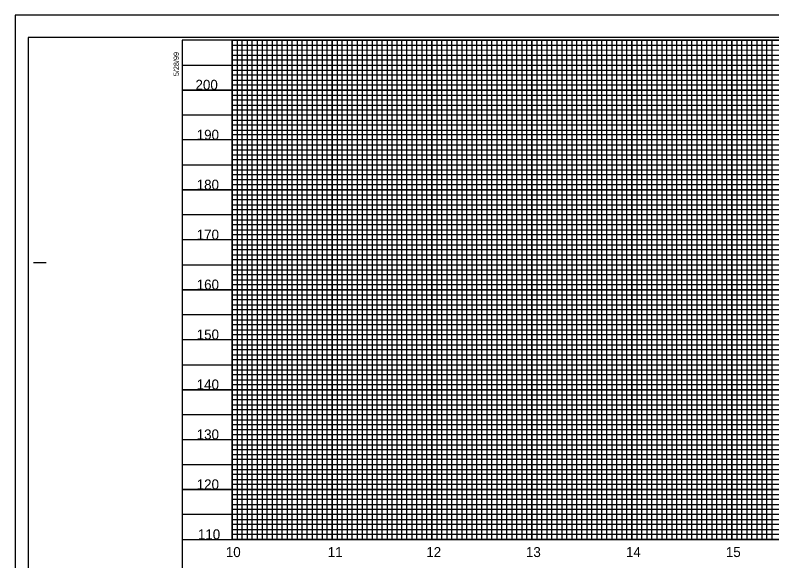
# Model space of a CAD drawing. Extents: x 1779926 to 1781610, y 602514 to 621564.
# Drawn here: x 1779926 to 1780683, y 603068 to 603614 of the extents above; entities that cross this region are included whole.
import ezdxf

# ---------------------------------------------------------------- set-up
doc = ezdxf.new("R2010")
doc.units = 0
for name, color, linetype in [('Exist Vertical Profile Horizontal Axis Label Major', 7, 'Continuous'), ('Exist Vertical Profile Vertical Axis Label', 7, 'Continuous'), ('Scratch_Level_0', 7, 'Continuous'), ('Sheet DOT Grid CELL', 7, 'Continuous'), ('Sheet Layout Profile Border Port 1', 7, 'Continuous'), ('Sheet Plot Border Inside CELL', 7, 'Continuous'), ('Sheet Plot Border Outside CELL', 7, 'Continuous'), ('Sheet Profile CELL', 7, 'Continuous'), ('Sheet Profile Grid Major CELL', 7, 'Continuous'), ('Sheet Profile Grid Middle CELL', 7, 'Continuous'), ('Sheet Profile Grid Minor CELL', 7, 'Continuous')]:
    doc.layers.add(name, color=color, linetype=linetype)

msp = doc.modelspace()

# ---------------------------------------------------------------- linework, layer by layer
at = {"layer": 'Scratch_Level_0'}
msp.add_lwpolyline([(1780142.96, 603089.44), (1780142.96, 603589.44), (1781392.96, 603589.44), (1781392.96, 603364.44), (1781542.96, 603364.44), (1781542.96, 603089.44)], close=True, dxfattribs=at)
at = {"layer": 'Sheet DOT Grid CELL'}
for p, q in [((1780142.96, 603089.45), (1780142.96, 603589.45)), ((1780192.96, 603089.45), (1780192.96, 603589.45)), ((1780242.96, 603089.45), (1780242.96, 603589.45)), ((1780292.96, 603089.45), (1780292.96, 603589.45)), ((1780342.96, 603089.45), (1780342.96, 603589.45)), ((1780392.96, 603089.45), (1780392.96, 603589.45)), ((1780442.96, 603089.45), (1780442.96, 603589.45)), ((1780492.96, 603089.45), (1780492.96, 603589.45)), ((1780542.96, 603089.45), (1780542.96, 603589.45)), ((1780592.96, 603089.45), (1780592.96, 603589.45)), ((1780642.96, 603089.45), (1780642.96, 603589.45)), ((1781392.91, 603539.45), (1780092.96, 603539.45)), ((1781392.91, 603489.45), (1780092.96, 603489.45)), ((1781392.96, 603439.45), (1780092.96, 603439.45)), ((1781392.91, 603389.45), (1780092.96, 603389.45)), ((1781592.96, 603339.45), (1780092.96, 603339.45)), ((1781592.96, 603289.45), (1780092.96, 603289.45)), ((1781592.96, 603239.45), (1780092.96, 603239.45)), ((1781592.96, 603189.45), (1780092.96, 603189.45)), ((1781592.96, 603139.45), (1780092.96, 603139.45))]:
    msp.add_line(p, q, dxfattribs=at)
at = {"layer": 'Sheet Layout Profile Border Port 1'}
msp.add_lwpolyline([(1780142.96, 603589.44), (1781392.91, 603589.45), (1781392.9, 603364.45), (1781542.96, 603364.44), (1781542.96, 603089.45), (1780142.96, 603089.44)], close=True, dxfattribs=at)
msp.add_lwpolyline([(1780142.96, 603428.4), (1780142.96, 603089.45), (1781542.96, 603089.45), (1781542.96, 603364.45)], dxfattribs=at)
at = {"layer": 'Sheet Plot Border Inside CELL'}
msp.add_lwpolyline([(1779938.96, 602536.9), (1781605.46, 602536.9), (1781605.46, 603592), (1779938.96, 603592)], close=True, dxfattribs=at)
at = {"layer": 'Sheet Plot Border Outside CELL'}
msp.add_lwpolyline([(1779925.96, 602514.45), (1781609.96, 602514.45), (1781609.96, 603614.45), (1779925.96, 603614.45)], close=True, dxfattribs=at)
at = {"layer": 'Sheet Profile CELL'}
for p, q in [((1779944.46, 603366.95), (1779956.96, 603366.95)), ((1780092.96, 603089.45), (1781592.96, 603089.45))]:
    msp.add_line(p, q, dxfattribs=at)
msp.add_lwpolyline([(1781592.96, 603589.45), (1780092.96, 603589.45), (1780092.96, 602539.45), (1781592.96, 602539.45)], close=True, dxfattribs=at)
at = {"layer": 'Sheet Profile Grid Major CELL'}
for points in [[(1780142.96, 603589.45), (1780142.96, 603089.45), (1780192.96, 603089.45), (1780192.96, 603589.45), (1780242.96, 603589.45), (1780242.96, 603089.45), (1780292.96, 603089.45), (1780292.96, 603589.45), (1780342.96, 603589.45), (1780342.96, 603089.45), (1780392.96, 603089.45), (1780392.96, 603589.45), (1780442.96, 603589.45), (1780442.96, 603089.45), (1780492.96, 603089.45), (1780492.96, 603589.45), (1780542.96, 603589.45), (1780542.96, 603089.45), (1780592.96, 603089.45), (1780592.96, 603589.45), (1780642.96, 603589.45), (1780642.96, 603089.45), (1780692.96, 603089.45)], [(1780092.96, 603539.45), (1781392.96, 603539.45)], [(1781392.96, 603489.45), (1780092.96, 603489.45), (1780092.96, 603439.45), (1781392.96, 603439.45)], [(1781392.91, 603389.45), (1780092.96, 603389.45), (1780092.96, 603339.45), (1781592.96, 603339.45)], [(1781592.96, 603289.45), (1780092.96, 603289.45), (1780092.96, 603239.45), (1781592.96, 603239.45)], [(1781592.96, 603189.45), (1780092.96, 603189.45), (1780092.96, 603189.45), (1780092.96, 603139.45), (1781592.96, 603139.45)]]:
    msp.add_lwpolyline(points, dxfattribs=at)
at = {"layer": 'Sheet Profile Grid Middle CELL'}
msp.add_line((1780092.96, 603564.45), (1781392.91, 603564.45), dxfattribs=at)
for points in [[(1780167.96, 603589.45), (1780167.96, 603089.45), (1780217.96, 603089.45), (1780217.96, 603589.45), (1780267.96, 603589.45), (1780267.96, 603089.45), (1780317.96, 603089.45), (1780317.96, 603589.45), (1780367.96, 603589.45), (1780367.96, 603089.45), (1780417.96, 603089.45), (1780417.96, 603589.45), (1780467.96, 603589.45), (1780467.96, 603089.45), (1780517.96, 603089.45), (1780517.96, 603589.45), (1780567.96, 603589.45), (1780567.96, 603089.45), (1780617.96, 603089.45), (1780617.96, 603589.45), (1780667.96, 603589.45), (1780667.96, 603089.45), (1780717.96, 603089.45)], [(1781392.96, 603514.45), (1780092.96, 603514.45), (1780092.96, 603464.45), (1781392.96, 603464.45)], [(1781392.91, 603414.45), (1780092.96, 603414.45), (1780092.96, 603364.45), (1781417.96, 603364.45)], [(1781592.96, 603314.45), (1780092.96, 603314.45), (1780092.96, 603264.45), (1781592.96, 603264.45)], [(1781592.96, 603214.45), (1780092.96, 603214.45), (1780092.96, 603164.45), (1781592.96, 603164.45)], [(1781592.96, 603114.45), (1780092.96, 603114.45)]]:
    msp.add_lwpolyline(points, dxfattribs=at)
at = {"layer": 'Sheet Profile Grid Minor CELL'}
for p, q in [((1780142.96, 603584.45), (1781392.96, 603584.45)), ((1780142.96, 603579.45), (1780142.96, 603579.45)), ((1781392.96, 603579.45), (1780142.96, 603579.1)), ((1780142.96, 603574.45), (1781392.96, 603574.45)), ((1781392.91, 603454.45), (1780142.96, 603454.45)), ((1781392.96, 603449.45), (1780142.96, 603449.45)), ((1781392.96, 603444.45), (1780142.96, 603444.45)), ((1780142.96, 603434.45), (1781392.96, 603434.45)), ((1781392.96, 603429.45), (1780142.96, 603429.45)), ((1780142.96, 603424.45), (1781392.96, 603424.45)), ((1781392.96, 603404.45), (1780142.96, 603404.45)), ((1780142.96, 603399.45), (1781392.96, 603399.45)), ((1781392.91, 603379.45), (1780142.96, 603379.45)), ((1780142.96, 603374.45), (1781392.91, 603374.45)), ((1781542.96, 603354.45), (1780142.96, 603354.45)), ((1780142.96, 603349.45), (1781542.96, 603349.45)), ((1781542.96, 603344.45), (1780142.96, 603344.45)), ((1780142.96, 603334.45), (1781542.96, 603334.45)), ((1781542.96, 603329.45), (1780142.96, 603329.45)), ((1780142.96, 603324.45), (1781542.96, 603324.45)), ((1781542.96, 603319.45), (1780142.96, 603319.45)), ((1780142.96, 603309.45), (1781542.96, 603309.45)), ((1781542.96, 603304.45), (1780142.96, 603304.45)), ((1780142.96, 603299.45), (1781542.96, 603299.45)), ((1781542.96, 603294.45), (1780142.96, 603294.45)), ((1780142.96, 603284.45), (1781542.96, 603284.45)), ((1781542.96, 603279.45), (1780142.96, 603279.45)), ((1780142.96, 603274.45), (1781542.96, 603274.45)), ((1781542.96, 603269.45), (1780142.96, 603269.45)), ((1780142.96, 603259.45), (1781542.96, 603259.45)), ((1781542.96, 603254.45), (1780142.96, 603254.45)), ((1780142.96, 603249.45), (1781542.96, 603249.45)), ((1781542.96, 603244.45), (1780142.96, 603244.45)), ((1780142.96, 603234.45), (1781542.96, 603234.45)), ((1781542.96, 603229.45), (1780142.96, 603229.45)), ((1780142.96, 603224.45), (1781542.96, 603224.45)), ((1781542.96, 603219.45), (1780142.96, 603219.45)), ((1780142.96, 603209.45), (1781542.96, 603209.45)), ((1781542.96, 603204.45), (1780142.96, 603204.45)), ((1781542.96, 603199.45), (1780142.96, 603199.45)), ((1781542.96, 603194.45), (1780142.96, 603194.45)), ((1780142.96, 603184.45), (1781542.96, 603184.45)), ((1781542.96, 603179.45), (1780142.96, 603179.45)), ((1780142.96, 603174.45), (1781542.96, 603174.45)), ((1781542.96, 603169.45), (1780142.96, 603169.45)), ((1780142.96, 603159.45), (1781542.96, 603159.45)), ((1781542.96, 603154.45), (1780142.96, 603154.45)), ((1780142.96, 603149.45), (1781542.96, 603149.45)), ((1781542.96, 603144.45), (1780142.96, 603144.45)), ((1780142.96, 603134.45), (1781542.96, 603134.45)), ((1781542.96, 603129.45), (1780142.96, 603129.45)), ((1780142.96, 603124.45), (1781542.96, 603124.45)), ((1781542.96, 603119.45), (1780142.96, 603119.45)), ((1780142.96, 603109.45), (1781542.96, 603109.45)), ((1781542.96, 603104.45), (1780142.96, 603104.45)), ((1780142.96, 603099.45), (1781542.96, 603099.45))]:
    msp.add_line(p, q, dxfattribs=at)
for points in [[(1780147.96, 603589.45), (1780147.96, 603089.45), (1780152.96, 603089.45), (1780152.96, 603589.45), (1780157.96, 603589.45), (1780157.96, 603089.45), (1780162.96, 603089.45), (1780162.96, 603589.45), (1780172.96, 603589.45), (1780172.96, 603089.45), (1780177.96, 603089.45), (1780177.96, 603589.45), (1780182.96, 603589.45), (1780182.96, 603089.45), (1780187.96, 603089.45), (1780197.96, 603089.45), (1780202.96, 603089.45), (1780202.96, 603589.45), (1780207.96, 603589.45), (1780207.96, 603089.45), (1780212.96, 603089.45), (1780212.96, 603589.45), (1780222.96, 603589.45), (1780222.96, 603089.45), (1780227.96, 603089.45), (1780227.96, 603589.45), (1780232.96, 603589.45), (1780232.96, 603089.45), (1780237.96, 603089.45), (1780237.96, 603589.45), (1780247.96, 603589.45), (1780247.96, 603089.45), (1780252.96, 603089.45), (1780252.96, 603589.45), (1780257.96, 603589.45), (1780257.96, 603089.45), (1780262.96, 603089.45), (1780262.96, 603589.45), (1780272.96, 603589.45), (1780272.96, 603089.45), (1780277.96, 603089.45), (1780277.96, 603589.45), (1780282.96, 603589.45), (1780282.96, 603089.45), (1780287.96, 603089.45), (1780287.96, 603589.45), (1780297.96, 603589.45), (1780297.96, 603089.45), (1780302.96, 603089.45), (1780302.96, 603589.45), (1780307.96, 603589.45), (1780307.96, 603089.45), (1780312.96, 603089.45), (1780312.96, 603589.45), (1780322.96, 603589.45), (1780322.96, 603089.45), (1780327.96, 603089.45), (1780327.96, 603589.45), (1780332.96, 603589.45), (1780332.96, 603089.45), (1780337.96, 603089.45), (1780337.96, 603589.45), (1780347.96, 603589.45), (1780347.96, 603089.45), (1780352.96, 603089.45), (1780352.96, 603589.45), (1780357.96, 603589.45), (1780357.96, 603089.45)], [(1780187.96, 603089.45), (1780187.96, 603589.45), (1780197.96, 603589.45), (1780197.96, 603089.45)], [(1780357.96, 603089.45), (1780362.96, 603089.45), (1780362.96, 603589.45), (1780372.96, 603589.45), (1780372.96, 603089.45), (1780377.96, 603089.45), (1780377.96, 603589.45), (1780382.96, 603589.45), (1780382.96, 603089.45), (1780387.96, 603089.45), (1780387.96, 603589.45), (1780397.96, 603589.45), (1780397.96, 603089.45), (1780402.96, 603089.45), (1780402.96, 603589.45), (1780407.96, 603589.45), (1780407.96, 603089.45), (1780412.96, 603089.45), (1780412.96, 603589.45), (1780422.96, 603589.45), (1780422.96, 603089.45), (1780427.96, 603089.45), (1780427.96, 603589.45), (1780432.96, 603589.45), (1780432.96, 603089.45), (1780437.96, 603089.45), (1780437.96, 603589.45), (1780447.96, 603589.45), (1780447.96, 603089.45), (1780452.96, 603089.45), (1780452.96, 603589.45), (1780457.96, 603589.45), (1780457.96, 603089.45), (1780462.96, 603089.45), (1780462.96, 603589.45), (1780472.96, 603589.45), (1780472.96, 603089.45), (1780477.96, 603089.45), (1780477.96, 603589.45), (1780482.96, 603589.45), (1780482.96, 603089.45), (1780487.96, 603089.45), (1780487.96, 603589.45), (1780497.96, 603589.45), (1780497.96, 603089.45), (1780502.96, 603089.45), (1780502.96, 603589.45), (1780507.96, 603589.45), (1780507.96, 603089.45), (1780512.96, 603089.45), (1780512.96, 603589.45), (1780522.96, 603589.45), (1780522.96, 603089.45), (1780527.96, 603089.45), (1780527.96, 603589.45), (1780532.96, 603589.45), (1780532.96, 603089.45), (1780537.96, 603089.45), (1780537.96, 603589.45), (1780547.96, 603589.45), (1780547.96, 603089.45), (1780552.96, 603089.45), (1780552.96, 603589.45), (1780557.96, 603589.45), (1780557.96, 603089.45), (1780562.96, 603089.45), (1780562.96, 603589.45), (1780572.96, 603589.45), (1780572.96, 603089.45), (1780577.96, 603089.45), (1780577.96, 603589.45), (1780582.96, 603589.45), (1780582.96, 603089.45), (1780587.96, 603089.45), (1780587.96, 603589.45), (1780597.96, 603589.45), (1780597.96, 603089.45), (1780602.96, 603089.45), (1780602.96, 603589.45), (1780607.96, 603589.45), (1780607.96, 603089.45), (1780612.96, 603089.45), (1780612.96, 603589.45), (1780622.96, 603589.45), (1780622.96, 603089.45), (1780627.96, 603089.45), (1780627.96, 603589.45), (1780632.96, 603589.45), (1780632.96, 603089.45), (1780637.96, 603089.45), (1780637.96, 603589.45), (1780647.96, 603589.45), (1780647.96, 603089.45), (1780652.96, 603089.45), (1780652.96, 603589.45), (1780657.96, 603589.45), (1780657.96, 603089.45), (1780662.96, 603089.45), (1780662.96, 603589.45), (1780672.96, 603589.45)], [(1780672.96, 603589.45), (1780672.96, 603089.45), (1780677.96, 603089.45), (1780677.96, 603589.45), (1780682.96, 603589.45), (1780682.96, 603089.45), (1780687.96, 603089.45)], [(1781392.96, 603569.45), (1780142.96, 603569.45), (1780142.96, 603559.45), (1781392.96, 603559.45)], [(1781392.91, 603554.45), (1780142.96, 603554.45), (1780142.96, 603549.45), (1781392.96, 603549.45)], [(1781392.96, 603544.45), (1780142.96, 603544.45), (1780142.96, 603534.45), (1781392.96, 603534.45)], [(1781392.96, 603529.45), (1780142.96, 603529.45), (1780142.96, 603524.45), (1781392.96, 603524.45)], [(1781392.96, 603519.45), (1780142.96, 603519.45), (1780142.96, 603509.45), (1781392.96, 603509.45)], [(1781392.96, 603504.45), (1780142.96, 603504.45), (1780142.96, 603499.45), (1781392.96, 603499.45)], [(1781392.96, 603494.45), (1780142.96, 603494.45), (1780142.96, 603484.45), (1781392.96, 603484.45)], [(1781392.96, 603479.35), (1780143.06, 603479.35), (1780143.06, 603474.45), (1781392.96, 603474.45)], [(1781392.96, 603469.45), (1780142.96, 603469.45), (1780142.96, 603459.45), (1781392.96, 603459.45)], [(1781392.91, 603419.45), (1780142.96, 603419.45), (1780142.96, 603409.45), (1781392.91, 603409.45)], [(1781392.91, 603394.45), (1780142.96, 603394.45), (1780142.96, 603384.45), (1781392.91, 603384.45)], [(1781392.91, 603369.45), (1780142.96, 603369.45), (1780142.96, 603359.45), (1781542.96, 603359.45)], [(1781542.96, 603094.45), (1780142.96, 603094.45)]]:
    msp.add_lwpolyline(points, dxfattribs=at)

# ---------------------------------------------------------------- texts
at = {"layer": 'Exist Vertical Profile Horizontal Axis Label Major'}
for s, p in [('10', (1780136.73, 603071.94)), ('11', (1780238.7, 603071.95)), ('12', (1780337.27, 603071.95)), ('13', (1780436.95, 603071.95)), ('14', (1780537, 603071.95)), ('15', (1780636.93, 603071.95))]:
    msp.add_text(s, height=10, dxfattribs=at).set_placement(p)
at = {"layer": 'Exist Vertical Profile Vertical Axis Label'}
for s, p in [('200', (1780106.39, 603539.7)), ('190', (1780107.59, 603489.7)), ('180', (1780107.59, 603439.7)), ('170', (1780107.59, 603389.7)), ('160', (1780107.59, 603339.7)), ('150', (1780107.59, 603289.7)), ('140', (1780107.59, 603239.7)), ('130', (1780107.59, 603189.7)), ('120', (1780107.59, 603139.7)), ('110', (1780108.79, 603089.7))]:
    msp.add_text(s, height=10, dxfattribs=at).set_placement(p)
at = {"layer": 'Sheet Profile CELL'}
msp.add_text('5/28/99', height=5.25, rotation=90, dxfattribs=at).set_placement((1780089.72, 603553.36))

doc.saveas('drawing.dxf')
